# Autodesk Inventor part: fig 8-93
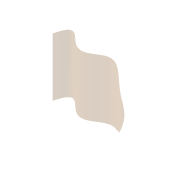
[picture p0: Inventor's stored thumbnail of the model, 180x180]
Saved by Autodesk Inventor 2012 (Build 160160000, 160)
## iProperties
Shininess: 64.0
Length Units: 11269
Angle Units: 11279
Time Units: 11290
Mass Units: 11283
Length Display Precision: 3
Angle Display Precision: 2
Compacted: True
Part Number: fig 8-93
Document SubType Name: Modeling
Created: 2003-08
Designer: Owner
Manufacturer: Standard
Standards Organization: Custom
Density: 1 g/cm^3
Material: Default
Density: 0.0
Volumn: 0.0
Area: 0.0
PropertySet Name: Model Information
Control State: 0
Master: False
Checked Out: False
Author: Owner
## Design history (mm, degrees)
sketch "Sketch1"
  geometry: 7 further points
  constraints: 7 other
  dimensions: "d0" = 80 horizontal distance of point (40, 1.742) point (-40, -4.065); "d1" = 40 horizontal distance of point (0, 0) point (-40, -4.065)
extrude_surface "ExtrusionSrf1" sketch "Sketch1" dims "d2" = 80, "d3" = 0
sketch "Sketch2"
  geometry: L1 (40, 0)-(40, -40) reference; L2 (-40, 0)-(-40, -40) reference; 7 further points
  constraints: 2 point on line, 7 other
extrude_surface "ExtrusionSrf2" sketch "Sketch2" dims "d4" = 80, "d5" = 0
workplane "Work Plane1"
sketch "Sketch4"
  geometry: L1 (70.027, 16.004)-(-4, 16.004); A1 r 29.004 centre (-4, -13) between (-4, 16.004) and (-2.981, -41.986)
  constraints: 2 end point, 2 point on circle, 1 centre point, 1 horizontal, 1 tangent
feature "Trim1" sketch "Sketch4"
body "Srf1"
body "Srf2"
other parameters: "d6" = -54.75
